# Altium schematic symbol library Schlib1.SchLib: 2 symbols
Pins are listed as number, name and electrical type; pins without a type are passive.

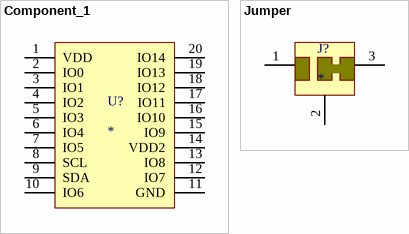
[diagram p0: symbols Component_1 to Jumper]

## Component_1
designator U?
footprint PCBComponent_1
pins: 1 VDD, 2 IO0, 3 IO1, 4 IO2, 5 IO3, 6 IO4, 7 IO5, 8 SCL, 9 SDA, 10 IO6, 11 GND, 12 IO7, 13 IO8, 14 VDD2, 15 IO9, 16 IO10, 17 IO11, 18 IO12, 19 IO13, 20 IO14

## Jumper
designator J?  (net tie, no BOM)
footprint JUMPER
pins: 1, 2, 3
